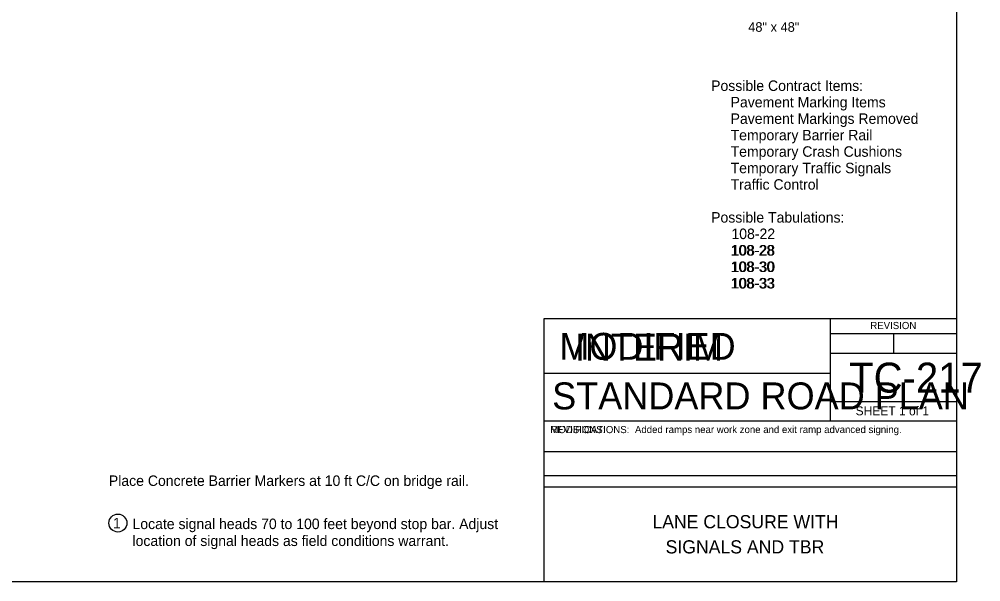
# Model space of a CAD drawing. Extents: x -2134934 to -2122394, y -2140205 to -2137036.
# Drawn here: x -2128661 to -2127057, y -2139046 to -2138106 of the extents above; entities that cross this region are included whole.
import ezdxf

# ---------------------------------------------------------------- set-up
doc = ezdxf.new("R2010")
doc.units = 0
for name, color, linetype in [('Barrier', 7, 'Continuous'), ('BridgeSuperStructureExisting', 7, 'Continuous'), ('Default', 7, 'Continuous'), ('Dimension', 7, 'Continuous'), ('dsnAlignmentCurveData', 7, 'Continuous'), ('dsnAlignmentTic', 7, 'Continuous'), ('dsnCellElements', 7, 'Continuous'), ('hwyPlanSheetShape', 7, 'Continuous')]:
    doc.layers.add(name, color=color, linetype=linetype)

msp = doc.modelspace()

# ---------------------------------------------------------------- linework, layer by layer
at = {"layer": 'BridgeSuperStructureExisting'}
msp.add_circle((-2128496.7, -2138947.8), 15, dxfattribs=at)
at = {"layer": 'Default'}
msp.add_lwpolyline([(-2130232, -2137035.9), (-2127097, -2137035.9), (-2127097, -2139045.9), (-2130232, -2139045.9)], close=True, dxfattribs=at)
at = {"layer": 'Dimension'}
for p, q in [((-2127307.9, -2138605.9), (-2127307.9, -2138697.3)), ((-2127307.9, -2138630.9), (-2127097, -2138630.9)), ((-2127202.4, -2138630.9), (-2127202.4, -2138664.1)), ((-2127307.9, -2138664.1), (-2127097, -2138664.1)), ((-2127785, -2138697.3), (-2127307.9, -2138697.3)), ((-2127307.9, -2138697.3), (-2127307.9, -2138777.3)), ((-2127097, -2138745.1), (-2127307.9, -2138745.1)), ((-2127785, -2138777.3), (-2127097, -2138777.3)), ((-2127785, -2138828.3), (-2127097, -2138828.3)), ((-2127785, -2138868.3), (-2127097, -2138868.3)), ((-2127785, -2138887.3), (-2127097, -2138887.3))]:
    msp.add_line(p, q, dxfattribs=at)
msp.add_lwpolyline([(-2127785, -2138605.9), (-2127097, -2138605.9), (-2127097, -2139045.9), (-2127785, -2139045.9)], close=True, dxfattribs=at)

# ---------------------------------------------------------------- texts
at = {"layer": 'Barrier'}
msp.add_text('48" x 48"', height=16, dxfattribs=at).set_placement((-2127444.7, -2138127.1))
at = {"layer": 'BridgeSuperStructureExisting'}
for s, p in [('1', (-2128504.8, -2138956.6)), ('Locate signal heads 70 to 100 feet beyond stop bar. Adjust ', (-2128472.3, -2138957.9)), ('location of signal heads as field conditions warrant.', (-2128472.3, -2138986.2))]:
    msp.add_text(s, height=17.5, dxfattribs=at).set_placement(p)
at = {"layer": 'Dimension'}
for s, height, p in [('REVISION', 12, (-2127240.9, -2138623.8)), ('TC-217', 50, (-2127276.2, -2138729.8)), ('STANDARD ROAD PLAN', 45.001, (-2127771.9, -2138757.9)), ('SHEET 1 of 1', 15, (-2127265.5, -2138767.9)), ('Added ramps near work zone and exit ramp advanced signing.', 12, (-2127633.7, -2138797.5)), ('LANE CLOSURE WITH', 22, (-2127604.6, -2138956.6)), ('SIGNALS AND TBR', 22, (-2127582.6, -2138998.6))]:
    msp.add_text(s, height=height, dxfattribs=at).set_placement(p)
at = {"layer": 'dsnAlignmentCurveData'}
msp.add_text('REVISIONS:', height=12, dxfattribs=at).set_placement((-2127775, -2138797.6))
at = {"layer": 'dsnAlignmentTic'}
for s, height, p in [('MODIFIED', 45, (-2127759.9, -2138675.1)), ('MODIFICATIONS:', 12, (-2127775, -2138797.6))]:
    msp.add_text(s, height=height, dxfattribs=at).set_placement(p)
at = {"layer": 'dsnCellElements'}
for s, p in [('Possible Contract Items:', (-2127506.6, -2138225.9)), ('     Pavement Marking Items', (-2127506.6, -2138253.4)), ('     Pavement Markings Removed', (-2127506.6, -2138280.9)), ('     Temporary Barrier Rail', (-2127506.6, -2138308.4)), ('     Temporary Crash Cushions', (-2127506.6, -2138335.9)), ('     Temporary Traffic Signals', (-2127506.6, -2138363.4)), ('     Traffic Control', (-2127506.6, -2138390.9)), ('Possible Tabulations:', (-2127506.6, -2138445.9)), ('108-22', (-2127472.7, -2138473.3)), ('108-22', (-2127472.7, -2138473.4)), ('     108-28', (-2127506.6, -2138500.9)), ('108-28', (-2127472.7, -2138500.9)), ('     108-30', (-2127506.6, -2138528.4)), ('108-30', (-2127472.7, -2138528.4)), ('     108-33', (-2127506.6, -2138555.9)), ('108-33', (-2127472.7, -2138555.9)), ('Place Concrete Barrier Markers at 10 ft C/C on bridge rail.', (-2128511.7, -2138885.8))]:
    msp.add_text(s, height=17.5, dxfattribs=at).set_placement(p)
at = {"layer": 'hwyPlanSheetShape'}
msp.add_text('INTERIM', height=45, dxfattribs=at).set_placement((-2127734, -2138676.3))

doc.saveas('drawing.dxf')
